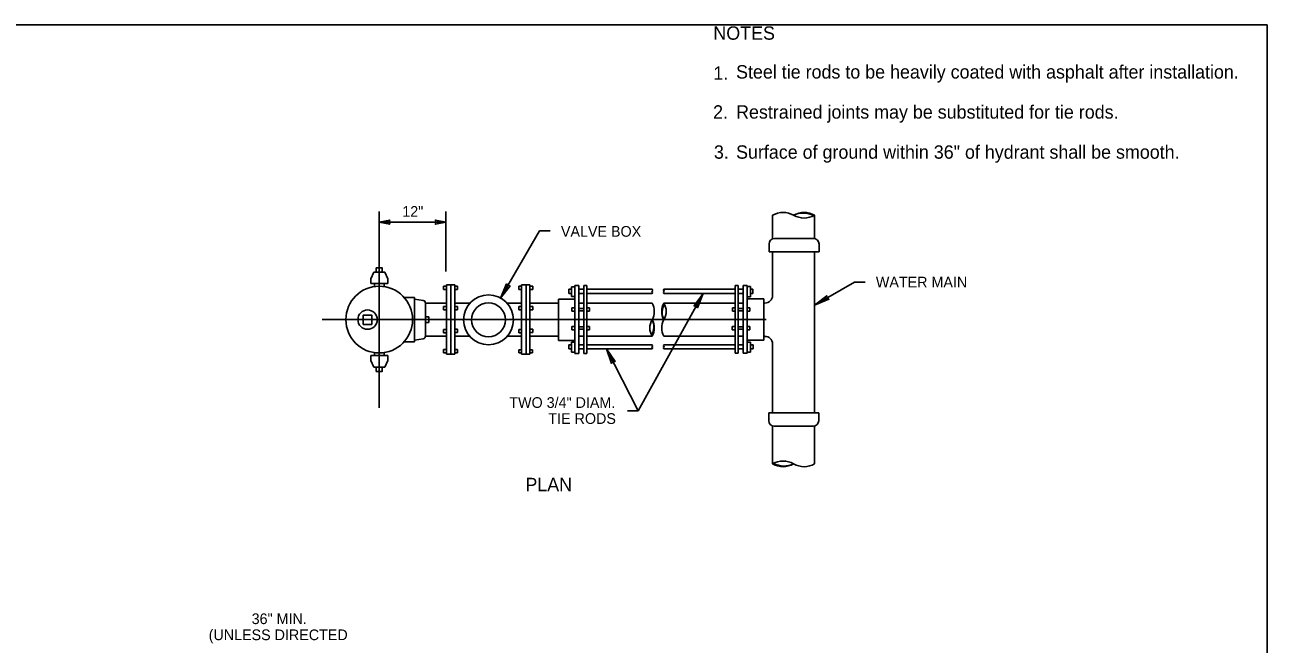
# Model space of a CAD drawing. Extents: x 99862 to 103151, y 100000 to 102076.
# Drawn here: x 101292 to 103151, y 101148 to 102076 of the extents above; entities that cross this region are included whole.
import ezdxf

# ---------------------------------------------------------------- set-up
doc = ezdxf.new("R2010")
doc.units = 0
for name, color, linetype in [('Level 1', 7, 'Continuous'), ('Level 15', 7, 'Continuous'), ('Level 18', 7, 'Continuous'), ('Level 20', 7, 'Continuous'), ('Level 6', 7, 'Continuous'), ('Level 60', 7, 'Continuous')]:
    doc.layers.add(name, color=color, linetype=linetype)

msp = doc.modelspace()

# ---------------------------------------------------------------- linework, layer by layer
at = {"layer": 'Level 1'}
for p, q in [((102397.7, 101659), (102399.5, 101659)), ((102397.7, 101609.3), (102399.5, 101609.3))]:
    msp.add_line(p, q, dxfattribs=at)
msp.add_lwpolyline([(99862, 99999.5), (103151, 99999.5), (103151, 102075.5), (99862, 102075.5)], close=True, dxfattribs=at)
at = {"layer": 'Level 15'}
for p, q in [((101822.3, 101796.1), (101822.3, 101502.4)), ((101922.1, 101780.1), (101822.3, 101780.1)), ((101922.1, 101796.1), (101922.1, 101706.1)), ((102004, 101666.3), (102062.3, 101767.2)), ((102062.3, 101767.2), (102078.3, 101767.2)), ((102473.8, 101656), (102533.5, 101690.4)), ((102549.5, 101690.4), (102533.5, 101690.4)), ((102307, 101673.3), (102210, 101497.6)), ((101737.1, 101634.3), (102401.1, 101634.3)), ((102162.2, 101590.4), (102210, 101497.6)), ((102194, 101497.6), (102210, 101497.6))]:
    msp.add_line(p, q, dxfattribs=at)
for points in [[(101822.3, 101780.1), (101838.1, 101777.1), (101837.3, 101780.1), (101838.1, 101783.2)], [(101922.1, 101780.1), (101906.4, 101777.1), (101907.1, 101780.1), (101906.4, 101783.2)], [(102004, 101666.3), (102018, 101684.6), (102014.9, 101685.2), (102012.8, 101687.6)], [(102307, 101673.3), (102298.6, 101651.9), (102296.5, 101654.2), (102293.4, 101654.7)], [(102473.8, 101656), (102492.1, 101669.9), (102492.7, 101666.8), (102495.1, 101664.8)], [(102162.2, 101590.4), (102175.3, 101571.4), (102172.2, 101571), (102170, 101568.7)]]:
    msp.add_lwpolyline(points, close=True, dxfattribs=at)
at = {"layer": 'Level 18'}
for p, q in [((101809.6, 101695.4), (101814.1, 101705.3)), ((101809.6, 101688.3), (101809.6, 101695.4)), ((101835.1, 101688.3), (101809.6, 101688.3)), ((101830.6, 101705.3), (101814.1, 101705.3)), ((101815.2, 101683.5), (101815.2, 101687.7)), ((101829.5, 101683.5), (101829.5, 101687.7)), ((101835.1, 101695.4), (101830.6, 101705.3)), ((101835.1, 101688.3), (101835.1, 101695.4)), ((101922.9, 101684.4), (101918.5, 101684.4)), ((101918.5, 101679.4), (101918.5, 101684.4)), ((101922.9, 101679.4), (101918.5, 101679.4)), ((101922.9, 101582.4), (101922.9, 101686.1)), ((101922.9, 101686.1), (101935.3, 101686.1)), ((101929.5, 101582.4), (101929.5, 101686.1)), ((101935.3, 101582.4), (101935.3, 101686.1)), ((101935.3, 101684.4), (101939.5, 101684.4)), ((101939.5, 101679.4), (101935.3, 101679.4)), ((101939.5, 101679.4), (101939.5, 101684.4)), ((102035.4, 101684.4), (102031.1, 101684.4)), ((102031.1, 101679.4), (102031.1, 101684.4)), ((102031.1, 101679.4), (102035.4, 101679.4)), ((102035.4, 101686.1), (102047.9, 101686.1)), ((102035.4, 101582.4), (102035.4, 101686.1)), ((102042, 101582.4), (102042, 101686.1)), ((102047.9, 101582.4), (102047.9, 101686.1)), ((102047.9, 101684.4), (102052, 101684.4)), ((102047.9, 101679.4), (102052, 101679.4)), ((102052, 101679.4), (102052, 101684.4)), ((102109.9, 101679.7), (102106.2, 101679.7)), ((102106.2, 101679.7), (102106.2, 101673.3)), ((102106.2, 101673.3), (102109.9, 101673.3)), ((102109.9, 101668.6), (102109.9, 101683.5)), ((102109.9, 101683.5), (102114.8, 101683.5)), ((102109.9, 101668.6), (102114.8, 101668.6)), ((102114.8, 101583.7), (102114.8, 101685.5)), ((102114.8, 101685.5), (102121.2, 101685.5)), ((102121.2, 101583.7), (102121.2, 101685.5)), ((102121.2, 101679.7), (102128.6, 101679.7)), ((102128.6, 101673.3), (102121.2, 101673.3)), ((102128.6, 101583.7), (102128.6, 101685.5)), ((102128.6, 101685.5), (102133.1, 101685.5)), ((102133.1, 101583.7), (102133.1, 101685.5)), ((102230.5, 101679.7), (102133.1, 101679.7)), ((102230.5, 101673.3), (102133.1, 101673.3)), ((102248.3, 101679.7), (102354.8, 101679.7)), ((102248.4, 101673.3), (102354.8, 101673.3)), ((102354.8, 101584.2), (102354.8, 101685.5)), ((102359.3, 101685.5), (102354.8, 101685.5)), ((102359.3, 101584.2), (102359.3, 101685.5)), ((102366.7, 101679.7), (102359.3, 101679.7)), ((102359.3, 101673.3), (102366.7, 101673.3)), ((102366.7, 101584.2), (102366.7, 101685.5)), ((102373.1, 101685.5), (102366.7, 101685.5)), ((102373.1, 101584.2), (102373.1, 101685.5)), ((102373.1, 101683.7), (102377.9, 101683.7)), ((102377.9, 101668.3), (102377.9, 101683.7)), ((102377.9, 101679.7), (102381.6, 101679.7)), ((102381.6, 101673.3), (102377.9, 101673.3)), ((102381.6, 101679.7), (102381.6, 101673.3)), ((101859.5, 101667.5), (101875, 101667.5)), ((101875, 101667.5), (101875, 101601)), ((101875, 101664.9), (101888, 101663)), ((101891.5, 101659), (101891.5, 101609.5)), ((101891.5, 101659), (101922.9, 101659)), ((101918.7, 101648.9), (101918.7, 101653.9)), ((101922.9, 101653.9), (101918.7, 101653.9)), ((101935.3, 101659), (101958.3, 101659)), ((101935.3, 101653.9), (101939.4, 101653.9)), ((101939.4, 101648.9), (101939.4, 101653.9)), ((102013.3, 101659), (102035.1, 101659)), ((102031.2, 101648.9), (102031.2, 101653.9)), ((102035.4, 101653.9), (102031.2, 101653.9)), ((102047.6, 101659), (102090.8, 101659)), ((102047.9, 101653.9), (102052, 101653.9)), ((102052, 101648.9), (102052, 101653.9)), ((102090.8, 101664.7), (102114.8, 101664.7)), ((102090.8, 101603), (102090.8, 101664.7)), ((102114.7, 101651.7), (102110.7, 101651.7)), ((102110.7, 101646.8), (102110.7, 101651.7)), ((102121.1, 101651), (102128.6, 101651)), ((102133.1, 101651.7), (102137.1, 101651.7)), ((102137.1, 101646.8), (102137.1, 101651.7)), ((102354.8, 101651.8), (102350.7, 101651.8)), ((102350.7, 101646.8), (102350.7, 101651.8)), ((102366.7, 101651), (102359.3, 101651)), ((102373.1, 101668.3), (102377.9, 101668.3)), ((102373.1, 101651.8), (102377.1, 101651.8)), ((102377.1, 101646.8), (102377.1, 101651.8)), ((101896.3, 101638.3), (101891.5, 101638.3)), ((101896.3, 101638.3), (101896.3, 101630)), ((101922.8, 101648.9), (101918.7, 101648.9)), ((101935.3, 101648.9), (101939.4, 101648.9)), ((102035.3, 101648.9), (102031.2, 101648.9)), ((102047.9, 101648.9), (102052, 101648.9)), ((102110.7, 101646.8), (102114.7, 101646.8)), ((102128.6, 101647.5), (102121.1, 101647.5)), ((102137.1, 101646.8), (102133.1, 101646.8)), ((102350.7, 101646.8), (102354.8, 101646.8)), ((102359.3, 101647.5), (102366.7, 101647.5)), ((102377.1, 101646.8), (102373.1, 101646.8)), ((101896.3, 101630), (101891.5, 101630)), ((101918.5, 101614.5), (101918.5, 101619.5)), ((101922.9, 101619.5), (101918.5, 101619.5)), ((101922.9, 101614.5), (101918.5, 101614.5)), ((101935.3, 101619.8), (101939.6, 101619.8)), ((101935.3, 101614.9), (101939.6, 101614.9)), ((101939.6, 101614.9), (101939.6, 101619.8)), ((102031.1, 101614.5), (102031.1, 101619.5)), ((102035.4, 101619.5), (102031.1, 101619.5)), ((102035.4, 101614.5), (102031.1, 101614.5)), ((102047.9, 101619.8), (102052.1, 101619.8)), ((102047.9, 101614.9), (102052.1, 101614.9)), ((102052.1, 101614.9), (102052.1, 101619.8)), ((102110.7, 101624), (102114.7, 101624)), ((102110.7, 101619.1), (102110.7, 101624)), ((102110.7, 101619.1), (102114.8, 101619.1)), ((102128.6, 101623.3), (102121.2, 101623.3)), ((102128.6, 101619.8), (102121.2, 101619.8)), ((102137.1, 101624), (102133.1, 101624)), ((102137.1, 101619.1), (102133.1, 101619.1)), ((102137.1, 101619.1), (102137.1, 101624)), ((102350.6, 101624.1), (102354.8, 101624.1)), ((102350.6, 101619.1), (102350.6, 101624.1)), ((102350.6, 101619.1), (102354.8, 101619.1)), ((102359.3, 101623.4), (102366.7, 101623.4)), ((102359.3, 101619.9), (102366.7, 101619.9)), ((102377.1, 101624.1), (102373.1, 101624.1)), ((102377.1, 101619.1), (102373.1, 101619.1)), ((102377.1, 101619.1), (102377.1, 101624.1)), ((101859.5, 101601), (101875, 101601)), ((101875, 101603.4), (101888, 101605.3)), ((101891.5, 101609.3), (101922.9, 101609.3)), ((101935.3, 101609.3), (101957.9, 101609.3)), ((102013.7, 101609.3), (102035.1, 101609.3)), ((102047.6, 101609.3), (102090.8, 101609.3)), ((102090.8, 101603), (102114.8, 101603)), ((102110, 101596.7), (102106.1, 101596.7)), ((102106.1, 101596.7), (102106.1, 101590.4)), ((102110, 101585.7), (102110, 101600.6)), ((102110, 101600.6), (102114.8, 101600.6)), ((102121.2, 101596.7), (102128.6, 101596.7)), ((102230.6, 101596.7), (102133.1, 101596.7)), ((102248.4, 101596.7), (102354.8, 101596.7)), ((102366.7, 101596.7), (102359.3, 101596.7)), ((102377.9, 101600.6), (102373.1, 101600.6)), ((102377.9, 101585.7), (102377.9, 101600.6)), ((102377.9, 101596.7), (102381.7, 101596.7)), ((102381.7, 101596.7), (102381.7, 101590.4)), ((101809.6, 101580.3), (101809.6, 101573.1)), ((101835.1, 101580.3), (101809.6, 101580.3)), ((101815.2, 101584.8), (101815.2, 101580.6)), ((101829.5, 101584.8), (101829.5, 101580.6)), ((101835.1, 101580.3), (101835.1, 101573.1)), ((101918.4, 101584.3), (101918.4, 101589.3)), ((101922.9, 101589.3), (101918.4, 101589.3)), ((101922.9, 101584.3), (101918.4, 101584.3)), ((101935.3, 101582.4), (101922.9, 101582.4)), ((101939.4, 101589.3), (101935.3, 101589.3)), ((101935.3, 101584.3), (101939.4, 101584.3)), ((101939.4, 101584.3), (101939.4, 101589.3)), ((102031, 101584.3), (102031, 101589.2)), ((102031, 101589.2), (102035.4, 101589.2)), ((102035.4, 101584.3), (102031, 101584.3)), ((102047.9, 101582.4), (102035.4, 101582.4)), ((102047.9, 101589.2), (102051.9, 101589.2)), ((102047.9, 101584.3), (102051.9, 101584.3)), ((102051.9, 101584.3), (102051.9, 101589.2)), ((102106.1, 101590.4), (102110, 101590.4)), ((102110, 101585.7), (102114.8, 101585.7)), ((102114.8, 101583.7), (102121.2, 101583.7)), ((102128.6, 101590.4), (102121.2, 101590.4)), ((102128.6, 101583.7), (102133.1, 101583.7)), ((102230.6, 101590.4), (102133.1, 101590.4)), ((102248.4, 101590.4), (102354.8, 101590.4)), ((102359.3, 101584.2), (102354.8, 101584.2)), ((102359.3, 101590.4), (102366.7, 101590.4)), ((102373.1, 101584.2), (102366.7, 101584.2)), ((102377.9, 101585.7), (102373.1, 101585.7)), ((102381.7, 101590.4), (102377.9, 101590.4)), ((101809.6, 101573.1), (101814.1, 101563.3)), ((101830.6, 101563.3), (101814.1, 101563.3)), ((101835.1, 101573.1), (101830.6, 101563.3))]:
    msp.add_line(p, q, dxfattribs=at)
for points in [[(101817.8, 101705.3), (101817.8, 101711.7), (101826.9, 101711.7), (101826.9, 101705.3)], [(101798.4, 101627.1), (101798.4, 101640.9), (101811.2, 101640.9), (101811.2, 101627.1)], [(101817.8, 101563.3), (101817.8, 101556.6), (101826.9, 101556.6), (101826.9, 101563.3)]]:
    msp.add_lwpolyline(points, close=True, dxfattribs=at)
for centre, radius in [((101822.3, 101634.2), 49.9), ((101985.8, 101633.9), 37.2), ((101985.8, 101633.9), 25.4), ((101804.8, 101634.2), 14.5)]:
    msp.add_circle(centre, radius, dxfattribs=at)
for centre, radius, start, end in [((102233.3, 101674.9), 3.19, 150, 210), ((102227.8, 101678.1), 3.19, 330, 30), ((102227.8, 101674.9), 3.19, 330, 30), ((102251.1, 101678.1), 3.19, 150, 210), ((102251.1, 101674.9), 3.19, 150, 210), ((102245.6, 101678.1), 3.19, 330, 30), ((101887.4, 101658.9), 4.16, 0, 81.5048), ((101887.4, 101609.5), 4.16, 278.4952, 0), ((102227.8, 101595.1), 3.19, 330, 30), ((102251.1, 101595.1), 3.19, 150, 210), ((102245.6, 101595.1), 3.19, 330, 30), ((102233.3, 101592), 3.19, 150, 210), ((102227.8, 101592), 3.19, 330, 30), ((102251.1, 101592), 3.19, 150, 210)]:
    msp.add_arc(centre, radius, start, end, dxfattribs=at)
at = {"layer": 'Level 6'}
for p, q in [((102410.8, 101755.7), (102410.8, 101790.4)), ((102473.8, 101755.7), (102473.8, 101790.5)), ((102405.6, 101735.7), (102405.6, 101747.4)), ((102413.9, 101755.7), (102472.2, 101755.7)), ((102480.4, 101735.7), (102480.4, 101747.4)), ((102405.6, 101735.7), (102480.4, 101735.7)), ((102410.8, 101670.3), (102410.8, 101735.7)), ((102473.8, 101494.5), (102473.8, 101735.7)), ((102121.2, 101659), (102128.6, 101659)), ((102133.1, 101659), (102230.5, 101659)), ((102248.3, 101659), (102354.8, 101659)), ((102359.3, 101659), (102366.7, 101659)), ((102397.7, 101665.3), (102373.1, 101665.3)), ((102397.7, 101603.5), (102397.7, 101665.3)), ((102121.2, 101609.3), (102128.6, 101609.3)), ((102133.1, 101609.3), (102230.6, 101609.3)), ((102248.4, 101609.3), (102354.8, 101609.3)), ((102359.4, 101609.3), (102366.7, 101609.3)), ((102397.7, 101603.5), (102373.1, 101603.5)), ((102410.8, 101494.5), (102410.8, 101597.9)), ((102405.1, 101494.5), (102405.1, 101482.8)), ((102479.9, 101494.5), (102405.1, 101494.5)), ((102479.9, 101494.5), (102479.9, 101482.8)), ((102410.8, 101418.3), (102410.8, 101474.5)), ((102471.6, 101474.5), (102413.4, 101474.5)), ((102473.8, 101418.3), (102473.8, 101474.5))]:
    msp.add_line(p, q, dxfattribs=at)
for centre, radius, start, end in [((102426.6, 101763.2), 31.5, 60, 120), ((102458.1, 101763.2), 31.5, 60, 120), ((102456.4, 101762.1), 31.7, 60.1832, 116.3935), ((102458.1, 101817.8), 31.5, 240, 300), ((102413.9, 101747.3), 8.31, 90, 180), ((102472.1, 101747.3), 8.31, 0, 90), ((102399.5, 101670.3), 11.3, 270, 0), ((102209, 101646.5), 24.9, 330, 30), ((102269.9, 101646.5), 24.9, 150, 210), ((102270.7, 101645.2), 25, 150.1832, 206.3935), ((102226.8, 101646.5), 24.9, 330, 30), ((102252.1, 101621.7), 24.9, 150, 210), ((102208.2, 101623), 25, 330.1832, 26.3935), ((102209, 101621.7), 24.9, 330, 30), ((102269.9, 101621.7), 24.9, 150, 210), ((102399.5, 101597.9), 11.3, 0, 90), ((102413.4, 101482.9), 8.31, 180, 270), ((102471.6, 101482.9), 8.31, 270, 0), ((102426.6, 101391), 31.5, 60, 120), ((102426.6, 101445.6), 31.5, 240, 300), ((102428.2, 101446.7), 31.7, 240.1832, 296.3935), ((102458.1, 101445.6), 31.5, 240, 300)]:
    msp.add_arc(centre, radius, start, end, dxfattribs=at)
at = {"layer": 'Level 60'}
msp.add_line((103151, 102075.5), (103151, 102075.5), dxfattribs=at)

# ---------------------------------------------------------------- texts
at = {"layer": 'Level 20'}
for s, height, p in [('NOTES', 20, (102322.3, 102053.2)), ('1.', 20, (102322.3, 101993.2)), ('Steel tie rods to be heavily coated with asphalt after installation.', 20, (102356.3, 101995.1)), ('2.', 20, (102321.9, 101935.1)), ('Restrained joints may be substituted for tie rods.', 20, (102356.3, 101935.1)), ('3.', 20, (102323.1, 101875.1)), ('Surface of ground within 36" of hydrant shall be smooth.', 20, (102356.3, 101875.1)), ('12"', 16, (101856.8, 101788.1)), ('VALVE BOX', 16, (102094.2, 101758.3)), ('WATER MAIN', 16, (102565.5, 101682.4)), ('TWO 3/4" DIAM.', 16, (102017, 101502.1)), ('TIE RODS', 16, (102075.4, 101478.1)), ('PLAN', 20, (102041, 101377.4)), ('36" MIN.', 16, (101631.4, 101178.4)), ('(UNLESS DIRECTED', 16, (101567.1, 101154.4))]:
    msp.add_text(s, height=height, dxfattribs=at).set_placement(p)

doc.saveas('drawing.dxf')
